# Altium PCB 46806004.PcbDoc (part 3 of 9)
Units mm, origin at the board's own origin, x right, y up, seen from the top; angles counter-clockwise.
Board outline 130 x 105 mm, 8 copper layers (Top Layer, P1-GND, L1-Signal, L2-Signal, L3-Signal, L4-Signal, P2-GND, Bottom Layer), stack 1.63 mm thick; 796 components, 496 nets, 2808 pads, 1195 vias.
Unrouted connection lines stored in the file: 1.
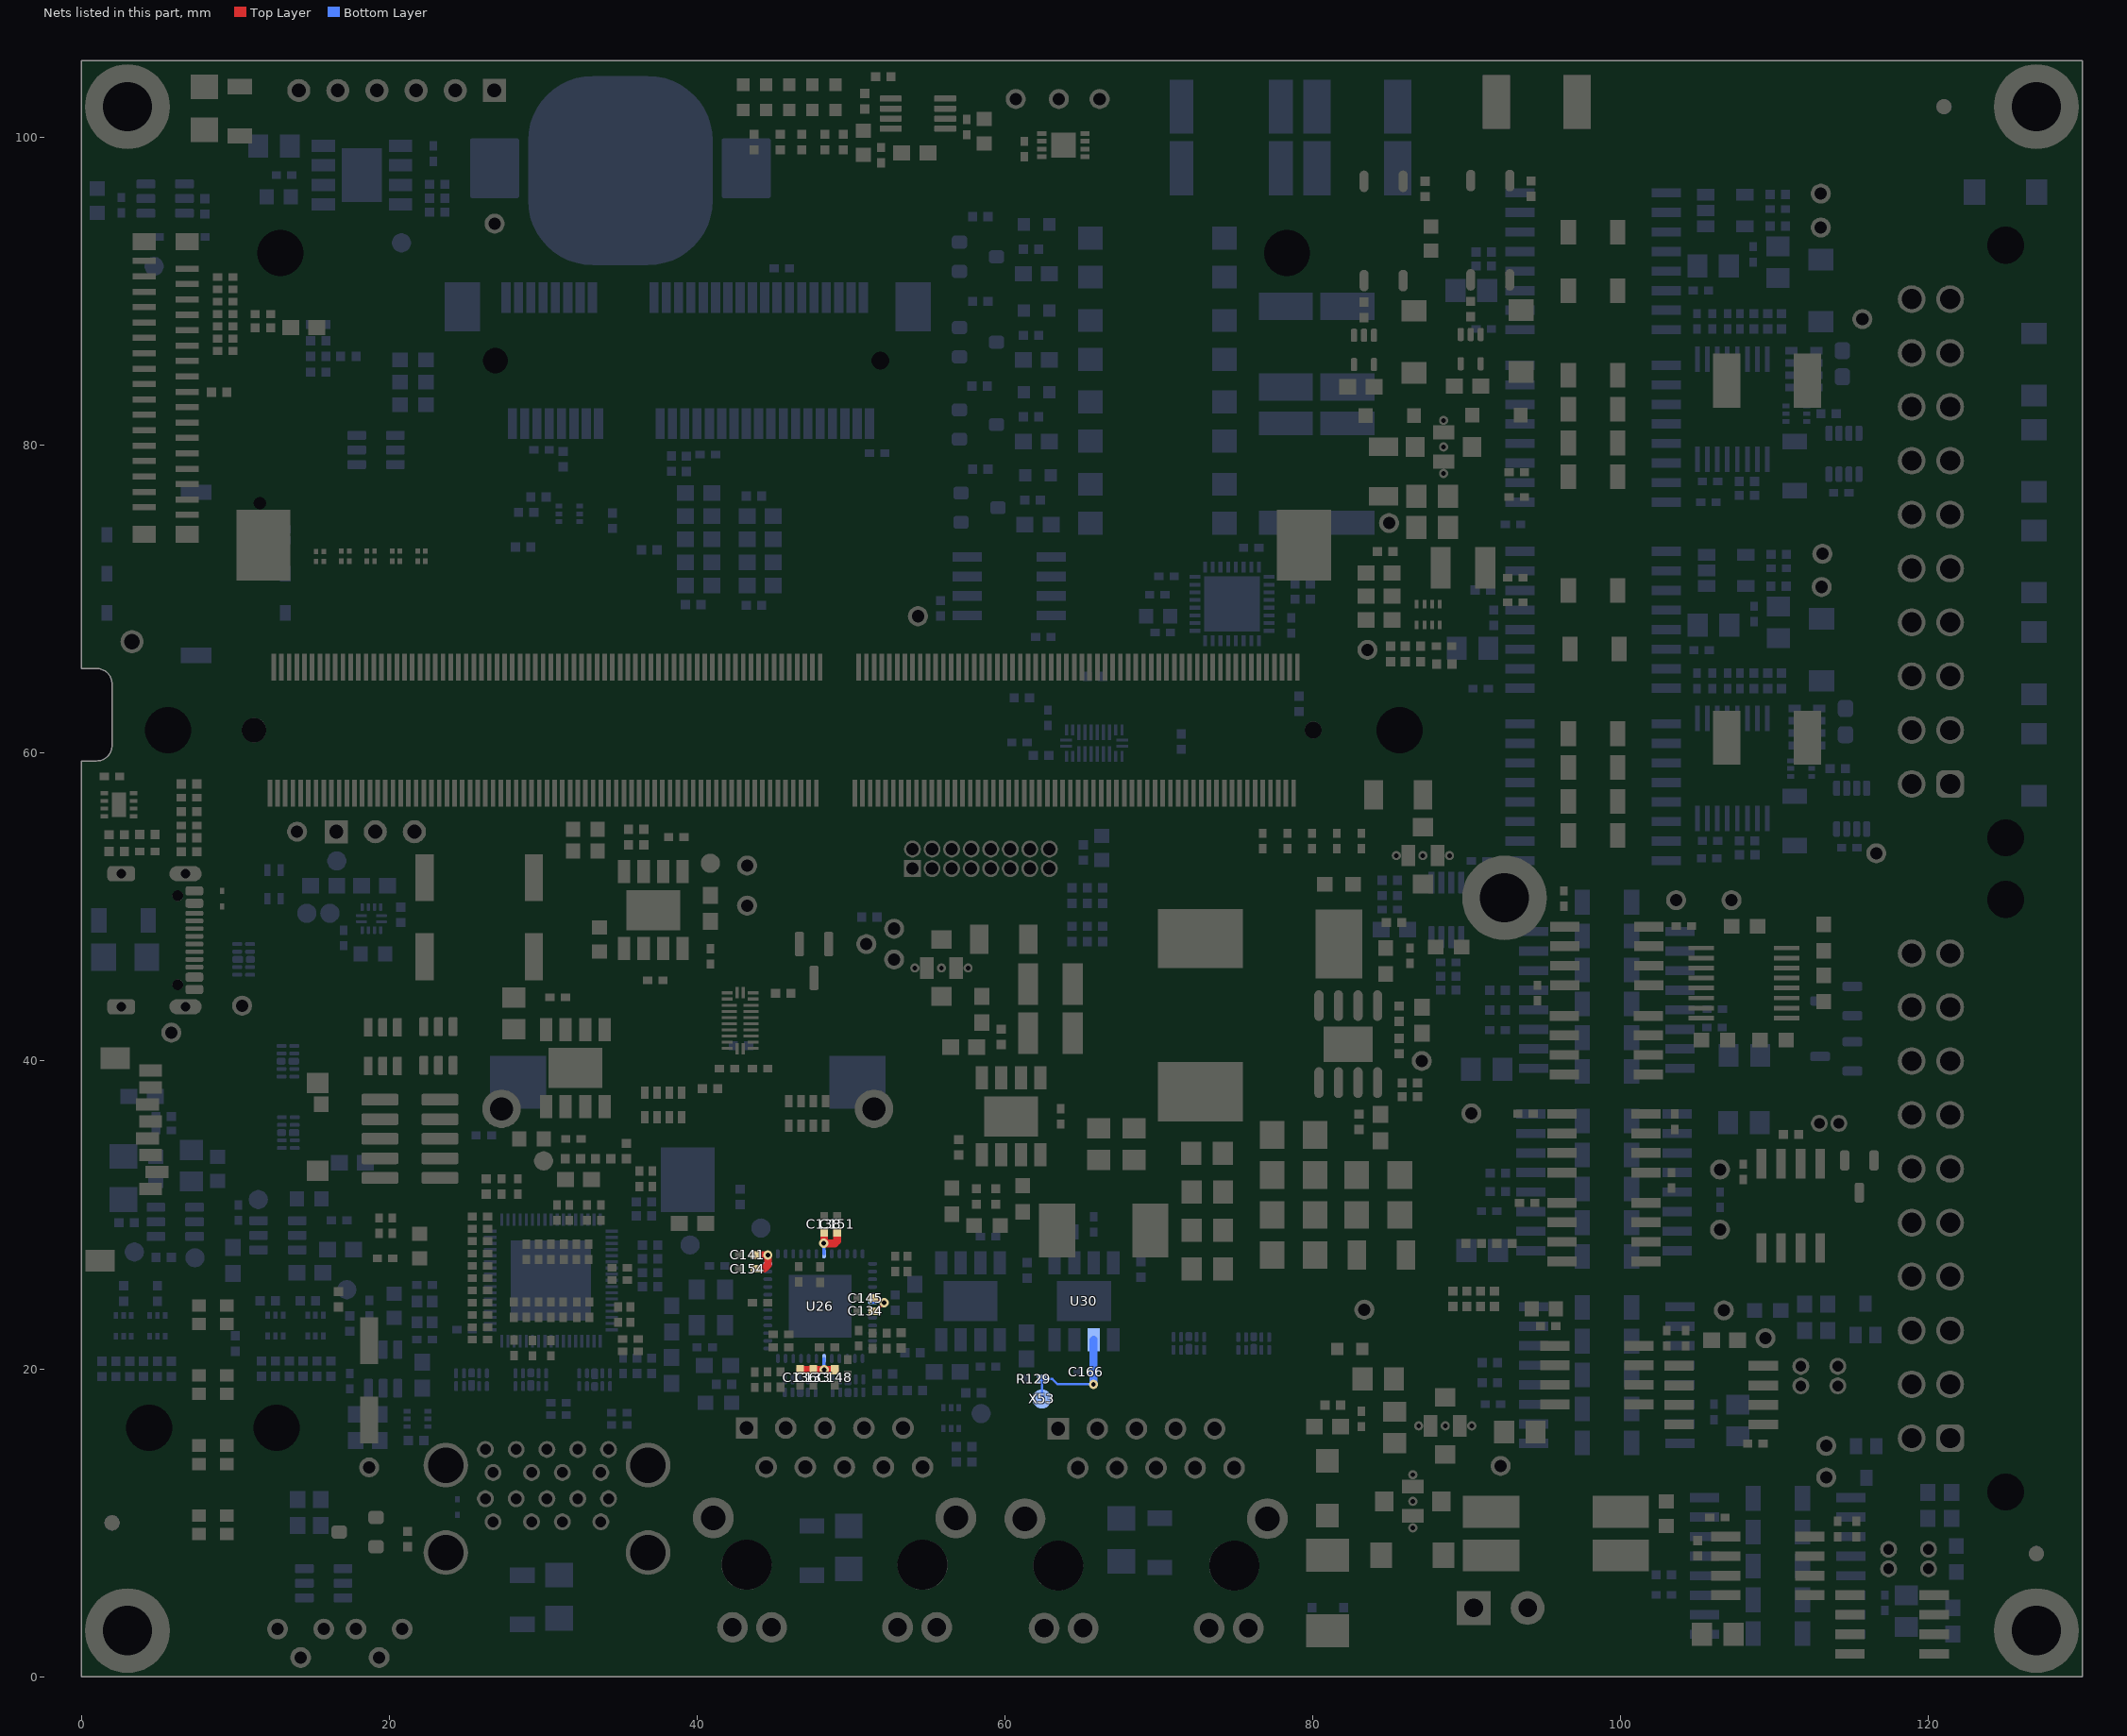
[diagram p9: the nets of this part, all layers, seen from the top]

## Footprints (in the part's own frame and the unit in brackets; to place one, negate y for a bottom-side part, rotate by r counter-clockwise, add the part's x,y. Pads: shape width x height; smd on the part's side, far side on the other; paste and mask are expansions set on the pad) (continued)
PW016 [mm] "16-TSSOP (0.173\", 4.40mm Width)"
  rect 0.3x1.65 smd: 1(-2.275,-2.775) 2(-1.625,-2.775) 3(-0.975,-2.775) 4(-0.325,-2.775) 5(0.325,-2.775) 6(0.975,-2.775) 7(1.625,-2.775) 8(2.275,-2.775) 9(2.275,2.775) 10(1.625,2.775) 11(0.975,2.775) 12(0.325,2.775) 13(-0.325,2.775) 14(-0.975,2.775) 15(-1.625,2.775) 16(-2.275,2.775)
  silkscreen extent -2.97,-2.89 2.55,1.55, body extent -2.55,-3.3 2.55,3.3, height 1.2
QFN40P160X160X40-12N [mm] "12-X2QFN (1.6x1.6), 12-Leads, Body 1,60x1,60mm, Pitch 0,40mm, IPC Medium Density"
  rrect50% 0.7x0.2 smd: 1(-0.65,0.2) 2(-0.65,-0.2) 7(0.65,-0.2) 8(0.65,0.2)
  rrect50% 0.2x0.5 smd: 3(-0.6,-0.75) 4(-0.2,-0.75) 5(0.2,-0.75) 6(0.6,-0.75) 9(0.6,0.75) 10(0.2,0.75) 11(-0.2,0.75) 12(-0.6,0.75)
  silkscreen extent -1.4,-1.19 1.19,1.19, body extent -0.8,-0.8 0.8,0.8, height 0.4
QFN50P500X500X90-33N-V [mm] "QFN,0.50mm pitch,square;32 pin,5.00mm L X 5.00mm W X 0.90mm H body (w/thermal tab)"
  rect 0.7x0.25 smd paste+0 mask+0: 1(-2.4,1.75) 2(-2.4,1.25) 3(-2.4,0.75) 4(-2.4,0.25) 5(-2.4,-0.25) 6(-2.4,-0.75) 7(-2.4,-1.25) 8(-2.4,-1.75) 17(2.4,-1.75) 18(2.4,-1.25) 19(2.4,-0.75) 20(2.4,-0.25) 21(2.4,0.25) 22(2.4,0.75) 23(2.4,1.25) 24(2.4,1.75)
  rect 0.25x0.7 smd paste+0 mask+0: 9(-1.75,-2.4) 10(-1.25,-2.4) 11(-0.75,-2.4) 12(-0.25,-2.4) 13(0.25,-2.4) 14(0.75,-2.4) 15(1.25,-2.4) 16(1.75,-2.4) 25(1.75,2.4) 26(1.25,2.4) 27(0.75,2.4) 28(0.25,2.4) 29(-0.25,2.4) 30(-0.75,2.4) 31(-1.25,2.4) 32(-1.75,2.4)
  rect 3.6x3.6 smd paste-20 mask+0: 33(0,0)
  silkscreen extent -3.42,-2.5 2.5,2.5, body extent -2.5,-2.5 2.5,2.5, height 0.9
QFN68_LT68B_CYP [mm]
  rect 0.808x0.204 smd paste+0 mask+0: 1(-3.947,3.2) 2(-3.947,2.8) 3(-3.947,2.4) 4(-3.947,2) 5(-3.947,1.6) 6(-3.947,1.2) 7(-3.947,0.8) 8(-3.947,0.4) 9(-3.947,0) 10(-3.947,-0.4) 11(-3.947,-0.8) 12(-3.947,-1.2) 13(-3.947,-1.6) 14(-3.947,-2) 15(-3.947,-2.4) 16(-3.947,-2.8) 17(-3.947,-3.2) 35(3.947,-3.2) 36(3.947,-2.8) 37(3.947,-2.4) 38(3.947,-2) 39(3.947,-1.6) 40(3.947,-1.2) 41(3.947,-0.8) 42(3.947,-0.4) 43(3.947,0) 44(3.947,0.4) 45(3.947,0.8) 46(3.947,1.2) 47(3.947,1.6) 48(3.947,2) 49(3.947,2.4) 50(3.947,2.8) 51(3.947,3.2)
  rect 0.204x0.808 smd paste+0 mask+0: 18(-3.2,-3.947) 19(-2.8,-3.947) 20(-2.4,-3.947) 21(-2,-3.947) 22(-1.6,-3.947) 23(-1.2,-3.947) 24(-0.8,-3.947) 25(-0.4,-3.947) 26(0,-3.947) 27(0.4,-3.947) 28(0.8,-3.947) 29(1.2,-3.947) 30(1.6,-3.947) 31(2,-3.947) 32(2.4,-3.947) 33(2.8,-3.947) 34(3.2,-3.947) 52(3.2,3.947) 53(2.8,3.947) 54(2.4,3.947) 55(2,3.947) 56(1.6,3.947) 57(1.2,3.947) 58(0.8,3.947) 59(0.4,3.947) 60(0,3.947) 61(-0.4,3.947) 62(-0.8,3.947) 63(-1.2,3.947) 64(-1.6,3.947) 65(-2,3.947) 66(-2.4,3.947) 67(-2.8,3.947) 68(-3.2,3.947)
  rect 5.207x5.207 smd paste-2.591 mask+0: 69(0,0)
  silkscreen extent -4.86,-4.86 4.86,4.86, body extent -4.05,-4.05 4.05,4.05, height 0.99
R0402_RESC1005L [mm] "Chip Resistor, Body 1.1x0.5mm, IPC High Density"
  rect 0.6x0.6 smd: 1(-0.5,0) 2(0.5,0)
  body extent -0.5,-0.25 0.5,0.25, height 0.35
R/0603 [mm] "RES 1/10W 0603"
  rect 1.1x1 smd: 1(-0.85,0) 2(0.85,0)
  silkscreen extent -1.65,-0.75 1.65,0.75, body extent -0.8,-0.4 0.8,0.4, height 0.45
R/0805 [mm] "RES 1/4W 0805 / From http://www.vishay.com/docs/28745/soldpads.pdf"
  rect 1.3x1.5 smd: 1(-1.025,0) 2(1.025,0)
  silkscreen extent -1.91,-0.99 1.91,0.99, body extent -1.15,-0.67 1.15,0.67, height 0.76
R/1206 [mm] "1206 (3216 Metric)"
  rect 1x1.6 smd: 1(-1.6,0) 2(1.6,0)
  silkscreen extent -2.36,-1.09 2.36,1.09, body extent -1.51,-0.77 1.51,0.77, height 0.55
R/2512 [mm] "2512 (6432 Metric)"
  rect 1.55x3.5 smd: 1(-3.225,0) 2(3.225,0)
  silkscreen extent -4.24,-2 4.24,2, body extent -3.2,-1.6 3.2,1.6, height 0.6
RESNET-1206-4 [mm]
  rect 0.5x0.8 smd: 1(-1.2,-0.8) 2(-0.4,-0.8) 3(0.4,-0.8) 4(1.2,-0.8) 5(1.2,0.8) 6(0.4,0.8) 7(-0.4,0.8) 8(-1.2,0.8)
  silkscreen extent -1.75,-0.87 1.7,0.87, body extent -1.6,-0.8 1.6,0.8, height 0.57
RGZ0048B [mm] "48-VQFN (7x7) (RGZ) Exposed Pad with vias"
  oval 0.6x0.24 smd paste+0 mask+0.051: 1(-3.4,2.75) 2(-3.4,2.25) 3(-3.4,1.75) 4(-3.4,1.25) 5(-3.4,0.75) 6(-3.4,0.25) 7(-3.4,-0.25) 8(-3.4,-0.75) 9(-3.4,-1.25) 10(-3.4,-1.75) 11(-3.4,-2.25) 12(-3.4,-2.75) 25(3.4,-2.75) 26(3.4,-2.25) 27(3.4,-1.75) 28(3.4,-1.25) 29(3.4,-0.75) 30(3.4,-0.25) 31(3.4,0.25) 32(3.4,0.75) 33(3.4,1.25) 34(3.4,1.75) 35(3.4,2.25) 36(3.4,2.75)
  oval 0.24x0.6 smd paste+0 mask+0.051: 13(-2.75,-3.4) 14(-2.25,-3.4) 15(-1.75,-3.4) 16(-1.25,-3.4) 17(-0.75,-3.4) 18(-0.25,-3.4) 19(0.25,-3.4) 20(0.75,-3.4) 21(1.25,-3.4) 22(1.75,-3.4) 23(2.25,-3.4) 24(2.75,-3.4) 37(2.75,3.4) 38(2.25,3.4) 39(1.75,3.4) 40(1.25,3.4) 41(0.75,3.4) 42(0.25,3.4) 43(-0.25,3.4) 44(-0.75,3.4) 45(-1.25,3.4) 46(-1.75,3.4) 47(-2.25,3.4) 48(-2.75,3.4)
  rect 4.1x4.1 smd paste-2.037 mask+0.051: 49(0,0)
  silkscreen extent -3.72,-3.72 3.72,3.72, body extent -3.5,-3.5 3.5,3.5, height 1
SAMTEC_FTSH-105-01-L-DV-K-TR [mm]
  rrect30% 0.76x2.4 smd: 1(-2.54,-1.95) 2(-2.54,1.95) 3(-1.27,-1.95) 4(-1.27,1.95) 5(0,-1.95) 6(0,1.95) 7(1.27,-1.95) 8(1.27,1.95) 9(2.54,-1.95) 10(2.54,1.95)
  silkscreen extent -3.43,-4.04 3.43,3.43, body extent -3.17,-2.92 3.18,2.92, height 6.1
Short_040 [mm]
  rrect50% 1.1x1 smd paste-2539.97 mask-2539.97: 1(-0.85,0) 2(0.85,0)
  Top Layer pour cut-out: -0.635,-0.508 0.635,-0.508 0.635,0.508 -0.635,0.508
  Top Layer region: -1.143,-0.381 1.143,-0.381 1.143,0.381 -1.143,0.381
SIM8055611400A [mm] "SIM NANO PUSH PULL 6P, 1.35MM"
  rect 1x0.7 smd: C1(2.54,-5.795) C2(0,-5.795) C3(-2.54,-5.795) C6(0,5.795) C7(-2.54,5.795)
  rect 0.5x0.7 smd: C5(2.19,5.795) CD(2.89,5.795)
  round 0.7 hole 0.8 unplated: MH1(4.6,4.15)
  round 1.5 hole 1: MH2(-4.4,-4.15)
  rect 1x2 smd: MP1(5.3,0) MP2(-5.3,0)
  Top Layer keep-out region: 3.15,2.953 1.95,2.953 1.95,3.953 3.15,3.953
  Top Layer keep-out region: 0.603,2.95 -0.597,2.95 -0.597,3.95 0.603,3.95
  Top Layer keep-out region: -1.937,2.95 -3.137,2.95 -3.137,3.95 -1.937,3.95
  Top Layer keep-out region: 1.943,-2.95 3.143,-2.95 3.143,-3.95 1.943,-3.95
  Top Layer keep-out region: -0.597,-2.95 0.603,-2.95 0.603,-3.95 -0.597,-3.95
  Top Layer keep-out region: -3.137,-2.95 -1.937,-2.95 -1.937,-3.95 -3.137,-3.95
  Top Layer keep-out region: -3.572,2.425 3.578,2.425 3.578,-2.425 -3.572,-2.425
  silkscreen extent -4.77,-6.7 4.77,6.1, body extent -5.4,-6.1 5.4,6.1, height 1.35
SMAJ [mil] "Diode SMA J-lead / DO-214AC SMA"
  rect 60x58 smd: 1(-70,0) 2(70,0)
  silkscreen extent -111,-63 125,63, body extent -102,-51 102,51, height 95
SMAJ_TRANSIL [mm] "Diode SMA J-lead Transil / DO-214AC SMA"
  rect 1.4x1.64 smd: 1(-2.015,0) 2(2.015,0)
  silkscreen extent -2.92,-1.6 3.28,1.6, body extent -2.6,-1.3 2.6,1.3, height 2.4
SOD123_ALT [mm] "SOD-123; 2 Leads; Body 2.7 x 1.6 mm, (LxW)"
  rect 0.9x0.95 smd: 1(-1.575,0) 3(1.575,0)
  silkscreen extent -1.45,-0.85 1.45,0.85, body extent -1.85,-0.8 1.85,0.8, height 1.27
SOD923_DIO [mm] "Diode, SOD-923, CASE 514AA"
  rect 0.393x0.3 smd paste+0 mask+0: 1(-0.507,0) 2(0.507,0)
  Top Layer keep-out region: -0.15,-0.249 -0.15,0.249 0.15,0.249 0.15,-0.249
  body extent -0.53,-0.32 0.53,0.32, height 0.43
SOIC-8 [mil] "8-SOIC (0.154\", 3.90mm Width)"
  rect 75x25 smd: 1(-107.5,75) 2(-107.5,25) 3(-107.5,-25) 4(-107.5,-75) 5(107.5,-75) 6(107.5,-25) 7(107.5,25) 8(107.5,75)
  silkscreen extent -67,-100 35,110, body extent -118,-96 118,96, height 67
SOIC-16 [mm] "SOIC127P1030X265-16M_[SOIC-16W]_JEDEC_MS-013AA"
  rect 0.6x1.9 smd: 1(-4.445,-4.75) 2(-3.175,-4.75) 3(-1.905,-4.75) 4(-0.635,-4.75) 5(0.635,-4.75) 6(1.905,-4.75) 7(3.175,-4.75) 8(4.445,-4.75) 9(4.445,4.75) 10(3.175,4.75) 11(1.905,4.75) 12(0.635,4.75) 13(-0.635,4.75) 14(-1.905,4.75) 15(-3.175,4.75) 16(-4.445,4.75)
  silkscreen extent -5.42,-4.87 5.23,3.4, body extent -5.25,-5.32 5.25,5.32, height 2.66
SOP254P700X210-4N [mm] "SOP, 4-Leads, Body 3,70x4,55mm, Pitch 2,54mm, IPC Medium Density"
  oval 1.4x0.6 smd: 1(-3.225,1.27) 2(-3.225,-1.27) 3(3.225,-1.27) 4(3.225,1.27)
  silkscreen extent -3.3,-1.85 2.27,1.85, body extent -3.5,-1.85 3.5,1.85, height 2.3
"SOP-9 TP" [mm] "SOIC, 8-Leads, Body 5,0x4,0mm (max), Pitch 1,27mm, IPC Medium Density"
  oval 2x0.6 smd: 1(-2.5,1.905) 2(-2.5,0.635) 3(-2.5,-0.635) 4(-2.5,-1.905) 5(2.5,-1.905) 6(2.5,-0.635) 7(2.5,0.635) 8(2.5,1.905)
  rect 2.3x3.2 smd: 9(0,0)
  silkscreen extent -2.52,-2.5 0.9,2.88, body extent -3,-2.45 3,2.45, height 2.05
"SOP-9 TP_ALT" [mm] "SOIC, 8-Leads, Body 5,0x4,0mm (max), Pitch 1,27mm, IPC Medium Density"
  rect 1.505x0.802 smd: 1(-2.5,1.905) 2(-2.5,0.635) 3(-2.5,-0.635) 4(-2.5,-1.905) 5(2.5,-1.905) 6(2.5,-0.635) 7(2.5,0.635) 8(2.5,1.905)
  rect 2.613x3.502 smd: 9(0,0)
  silkscreen extent -2.52,-2.5 0.9,2.88, body extent -3,-2.45 3,2.45, height 1.45
SOT23 [mm]
  rrect50% 0.85x1 smd: 1(-0.95,-1.2) 2(0.95,-1.2) 3(0,1.2)
  silkscreen extent -1.9,-1.32 1.28,1.2, body extent -1.45,-1.4 1.45,1.4, height 1.3
SOT23-5 [mil] "SOT23-5, JEDEC MO-178 variation AA, 5-lead SMD package, most material condition"
  rect 30x45 smd: 1(-40,-50) 2(0,-50) 3(40,-50) 4(40,50) 5(-40,50)
  silkscreen extent -89,-87 65,87, body extent -57,-55 57,55, height 57
SOT23-6 [mm]
  rrect25% 0.58x1.21 smd: 1(-0.95,-1.255) 2(0,-1.255) 3(0.95,-1.255) 4(0.95,1.255) 5(0,1.255) 6(-0.95,1.255)
  silkscreen extent -1.73,-1.37 1.56,0.8, body extent -1.45,-1.4 1.45,1.4, height 1.45
sot23-6 [mm]
  rrect25% 0.58x1.21 smd: 1(-0.95,-1.255) 2(0,-1.255) 3(0.95,-1.255) 4(0.95,1.255) 5(0,1.255) 6(-0.95,1.255)
  silkscreen extent -1.73,-1.37 1.56,0.8, body extent -1.45,-1.4 1.45,1.4, height 1.45
SOT23_M [mm]
  rrect50% 1.6x0.6 smd: 1(-1.1,0.95) 2(-1.1,-0.95) 3(1.1,0)
  silkscreen extent -1.22,-1.5 0.7,1.93, body extent -1.4,-1.45 1.4,1.45, height 1.3
SOT23_N [mm] "SOT23, 3-Leads, Body 2.9x1.3mm, Pitch 0.95mm, Lead Span 2.3mm, IPC Medium Density"
  rrect50% 1.3x0.6 smd: 1(-1.05,0.95) 2(-1.05,-0.95) 3(1.05,0)
  silkscreen extent -1.18,-1.5 0.7,1.92, body extent -1.4,-1.45 1.4,1.45, height 1.3
SOT353-5N [mm] "SOT353, SC70, 5-Leads, Body 2x1.3mm, Pitch 0.65mm, Lead Span 2.1mm, IPC Medium Density"
  rrect50% 0.85x0.4 smd: 1(-0.95,0.65) 2(-0.95,0) 3(-0.95,-0.65) 4(0.95,-0.65) 5(0.95,0.65)
  silkscreen extent -1.07,-1.1 0.18,1.32, body extent -1.2,-1.1 1.2,1.1, height 1.1
SOT563 [mm]
  rect 0.45x0.3 smd: 1(-0.675,0.5) 2(-0.675,0) 3(-0.675,-0.5) 4(0.675,-0.5) 5(0.675,0) 6(0.675,0.5)
  silkscreen extent -1.18,-0.66 0.24,0.66, body extent -0.81,-0.8 0.81,0.8, height 0.59
SOT-323 [mm] "SOT-323/SC-70; 3 Leads; Body 2.2 x 2.2 mm, inc. leads (LxW max)"
  rect 0.8x1.05 smd: 1(-0.65,-1.025) 2(0.65,-1.025) 3(0,1.025)
  silkscreen extent -1.52,-1.17 1.1,0.89, body extent -1.1,-1.12 1.1,1.12, height 1.1
"T_AMPHENOL_ GSB311231HR" [mm]
  round 1.1 hole 0.7: L1(-3.5,-1.35) L2(-1,-1.35) L3(1,-1.35) L4(3.5,-1.35) L5(4,0.15) L6(2,0.15) L7(0,0.15) L8(-2,0.15) L9(-4,0.15) U1(-3.5,1.85) U2(-1,1.85) U3(1,1.85) U4(3.5,1.85) U5(4,3.35) U6(2,3.35) U7(0,3.35) U8(-2,3.35) U9(-4,3.35)
  round 2.9 hole 2.3: S1(-6.57,-3.35) S2(-6.57,2.33) S3(6.57,2.33) S4(6.57,-3.35)
  silkscreen extent -6.8,-11.02 6.8,4.72, body extent -7.79,-15.13 7.79,4.57, height 16.13
T_KEYSTONE_3000 [mm] "Battery Holder"
  rrect70% 12x12.3 smd paste-11: 1(0,-0.15)
  rrect10% 3.2x3.9 smd: 2(-8.17,0) 2(8.17,0)
  silkscreen extent -6.63,-6.75 6.63,6.3, body extent -9.47,-6.72 9.47,5.34, height 3.16
T_TORADEX_LOGO [mm] "Toradex Logo in copper, no soldermask"
  Top Layer lines w0.15: -7.115,-0.198 cw(c-7.136,-0.05) -7.286,-0.05 cw(c-7.136,-0.05) -7.115,0.099 ; -7.116,-0.05 -7,-0.05 ; -7.044,-0.26 ccw(c-6.322,-0.05) -5.621,-0.319 ; -7.044,0.16 cw(c-6.322,-0.05) -5.621,0.22 ; -6.911,-0.118 ccw(c-7.104,-0.277) -7,-0.05 ; -6.911,0.019 cw(c-7.104,0.178) -7,-0.05 ; -6.764,-0.4 ccw(c-6.322,-0.05) -5.955,-0.477 cw(c-5.738,-0.05) -6.087,-0.379 cw(c-6.436,-0.05) -6.916,-0.05 cw(c-6.436,-0.05) -6.087,0.28 cw(c-5.738,-0.05) -5.955,0.378 ccw(c-6.322,-0.05) -6.764,0.301 ; -6.484,-0.59 ccw(c-6.436,-0.05) -6.087,-0.465 ccw(c-5.738,-0.05) -6.067,-0.481 cw(c-6.322,-0.05) -6.192,-0.533 ; -6.484,0.491 cw(c-6.436,-0.05) -6.087,0.366 cw(c-5.738,-0.05) -6.067,0.382 ccw(c-6.322,-0.05) -6.192,0.434 ; -5.636,-0.331 cw(c-5.738,-0.05) -5.636,0.232 ; 4.083,-0.046 4.702,-0.046 5.383,-0.046 ccw(c4.702,-0.05) 5.214,-0.499 ; 4.087,-0.116 4.702,-0.116 5.45,-0.116 ccw(c4.702,-0.05) 5.304,-0.499 5.127,-0.499 cw(c4.702,-0.05) 5.317,0.017 4.702,0.017 4.087,0.017 ; -7.241,-0.05 ccw(c-7.136,-0.05) -7.121,-0.153 ; -7.241,-0.05 ccw(c-7.136,-0.05) -7.121,-0.153 ; -7.241,-0.05 cw(c-7.136,-0.05) -7.121,0.054 ccw(c-7.104,0.178) -6.984,0.143 cw(c-6.322,-0.05) -5.732,0.305 ccw(c-5.738,-0.05) -6.087,0.015 ccw(c-6.436,-0.05) -6.087,-0.114 ccw(c-5.738,-0.05) -5.732,-0.404 cw(c-6.322,-0.05) -6.984,-0.242 ccw(c-7.104,-0.277) -7.121,-0.153 ; -7.178,-0.05 ccw(c-7.136,-0.05) -7.13,-0.091 cw(c-7.104,-0.277) -6.924,-0.225 ccw(c-6.322,-0.05) -5.844,-0.453 cw(c-5.738,-0.05) -6.087,-0.278 cw(c-6.436,-0.05) -6.087,0.179 cw(c-5.738,-0.05) -5.844,0.354 ccw(c-6.322,-0.05) -6.924,0.126 cw(c-7.104,0.178) -7.13,-0.008 ccw(c-7.136,-0.05) -7.178,-0.05 ; -6.736,-0.05 cw(c-6.436,-0.05) -6.136,-0.05 cw(c-6.436,-0.05) -6.736,-0.05 ; -5.194,-0.05 ccw(c-5.044,-0.05) -4.894,-0.05 ccw(c-5.044,-0.05) -5.194,-0.05 ; -5.149,-0.05 cw(c-5.044,-0.05) -4.939,-0.05 cw(c-5.044,-0.05) -5.149,-0.05 ; -5.086,-0.05 ccw(c-5.044,-0.05) -5.002,-0.05 ccw(c-5.044,-0.05) -5.086,-0.05 ; -4.498,-0.05 ccw(c-4.348,-0.05) -4.198,-0.05 ccw(c-4.348,-0.05) -4.498,-0.05 ; -4.453,-0.05 cw(c-4.348,-0.05) -4.243,-0.05 cw(c-4.348,-0.05) -4.453,-0.05 ; -4.39,-0.05 ccw(c-4.348,-0.05) -4.306,-0.05 ccw(c-4.348,-0.05) -4.39,-0.05 ; -4.322,0.994 -3.523,0.994 -3.523,-0.75 -3.372,-0.75 -3.372,0.994 -2.603,0.994 -2.603,1.125 -4.218,1.125 -4.322,0.994 ; -4.192,1.057 -3.46,1.057 -3.46,-0.688 -3.434,-0.688 -3.434,1.057 -2.665,1.057 -2.665,1.062 -4.188,1.062 -4.192,1.057 ; -2.827,-0.05 ccw(c-2.076,-0.05) -1.324,-0.05 ccw(c-2.076,-0.05) -2.827,-0.05 ; -2.764,-0.05 ccw(c-2.076,-0.05) -1.387,-0.05 ccw(c-2.076,-0.05) -2.764,-0.05 ; -2.694,-0.05 ccw(c-2.076,-0.05) -1.457,-0.05 ccw(c-2.076,-0.05) -2.694,-0.05 ; -0.939,-0.75 -0.806,-0.75 -0.806,-0.05 cw(c-0.188,-0.05) -0.009,0.542 cw(c0.958,-0.05) 0.071,0.656 ccw(c-0.188,-0.05) -0.939,-0.05 -0.939,-0.75 ; -0.877,-0.688 -0.869,-0.688 -0.869,-0.05 cw(c-0.188,-0.05) -0.037,0.615 cw(c0.958,-0.049) -0.032,0.621 ccw(c-0.188,-0.05) -0.877,-0.05 -0.877,-0.688 ; 0.207,-0.05 ccw(c0.958,-0.05) 1.576,-0.476 1.576,-0.75 1.709,-0.75 1.709,-0.05 ccw(c0.958,-0.05) 0.207,-0.05 ; 0.269,-0.05 ccw(c0.958,-0.05) 1.639,-0.153 1.639,-0.688 1.647,-0.688 1.647,-0.05 ccw(c0.958,-0.05) 0.269,-0.05 ; 0.339,-0.05 ccw(c0.958,-0.05) 1.576,-0.05 ccw(c0.958,-0.05) 0.339,-0.05 ; 2.053,-0.05 cw(c2.804,-0.05) 3.423,0.377 3.423,1.125 3.556,1.125 3.556,-0.05 cw(c2.804,-0.05) 2.053,-0.05 ; 2.116,-0.05 cw(c2.804,-0.05) 3.485,0.054 3.485,1.062 3.493,1.062 3.493,-0.05 cw(c2.804,-0.05) 2.116,-0.05 ; 2.186,-0.05 ccw(c2.804,-0.05) 3.423,-0.05 ccw(c2.804,-0.05) 2.186,-0.05 ; 5.623,-0.75 5.791,-0.75 6.314,-0.086 6.835,-0.75 6.995,-0.75 6.403,0.006 6.919,0.664 6.749,0.664 6.314,0.1 5.879,0.664 5.716,0.664 6.23,0.006 5.623,-0.75 ; 5.753,-0.688 5.761,-0.688 6.315,0.015 6.865,-0.688 6.866,-0.688 6.323,0.006 6.79,0.602 6.78,0.602 6.314,-0.002 5.849,0.602 5.844,0.602 6.309,0.005 5.753,-0.688
TestPoint_1 [mm]
  round 1.3 hole 0.8: 1(0,0)
  silkscreen extent -0.9,-0.9 0.9,0.9
TestPoint_3 [mm]
  round 1.25 smd paste-1.25: 1(0,0)
TLP241A_TP1 [mm] "TOSHIBA TLP241A_TP1"
  rect 1.6x1.5 smd paste+0 mask+0: 1(-4.35,1.27) 2(-4.35,-1.27) 3(4.35,-1.27) 4(4.35,1.27)
  silkscreen extent -4.85,-2.54 3.45,2.55, body extent -5,-2.41 5,2.41, height 4.24
TSOT-23-8_TEX [mil] "SOT-23-8, TSOT-23-8, Texas DDF0008A"
  rrect50% 39.5x18 smd paste-1.97 mask+3.94: 1(-52.25,38.39) 2(-52.25,12.8) 3(-52.25,-12.79) 4(-52.25,-38.38) 5(52.25,-38.38) 6(52.25,-12.79) 7(52.25,12.8) 8(52.25,38.39)
  silkscreen extent -58,-63 38,67, body extent -55,-57 55,57, height 39
TSSO3x5-G8/X.35 [mm] "TSSOP-8P065 Shrink Small Outline; 8 Leads; Body Width 3 mm; Pitch 0.65 mm"
  rrect25% 0.4x1.42 smd: 1(-0.975,-1.77) 2(-0.325,-1.77) 3(0.325,-1.77) 4(0.975,-1.77) 5(0.975,1.77) 6(0.325,1.77) 7(-0.325,1.77) 8(-0.975,1.77)
  silkscreen extent -1.65,-2.11 1.52,0.8, body extent -1.47,-2 1.47,2, height 1.3
TSSOP16 [mm]
  rect 1.65x0.3 smd: 1(-3.25,2.275) 2(-3.25,1.625) 3(-3.25,0.975) 4(-3.25,0.325) 5(-3.25,-0.325) 6(-3.25,-0.975) 7(-3.25,-1.625) 8(-3.25,-2.275) 9(3.25,-2.275) 10(3.25,-1.625) 11(3.25,-0.975) 12(3.25,-0.325) 13(3.25,0.325) 14(3.25,0.975) 15(3.25,1.625) 16(3.25,2.275)
  silkscreen extent -2.89,-2.55 1.55,2.97, body extent -3.3,-2.55 3.3,2.55, height 1.2
UQFN-24 [mm]
  rect 0.7x0.2 smd paste-0.337 mask+0.05: 1(-0.85,1.8) 2(-0.85,1.4) 9(-0.85,-1.4) 10(-0.85,-1.8) 13(0.85,-1.8) 14(0.85,-1.4) 21(0.85,1.4) 22(0.85,1.8)
  rect 1x0.2 smd paste-0.487 mask+0.05: 3(-0.7,1) 4(-0.7,0.6) 5(-0.7,0.2) 6(-0.7,-0.2) 7(-0.7,-0.6) 8(-0.7,-1) 15(0.7,-1) 16(0.7,-0.6) 17(0.7,-0.2) 18(0.7,0.2) 19(0.7,0.6) 20(0.7,1)
  rect 0.2x0.75 smd paste-0.362 mask+0.05: 11(-0.2,-1.825) 12(0.2,-1.825) 23(0.2,1.825) 24(-0.2,1.825)
  silkscreen extent -1.88,-2.25 1.36,2.25, body extent -1,-2 1,2, height 0.55
WEIDMULLER_1728700000 [mm] "TERM BLOCK HDR 20POS 90DEG 3.5MM"
  rrect50% 1.8x1.8 hole 1.3 paste-2539.97: 1(-15.75,0.55)
  round 1.8 hole 1.3 paste-2539.97: 2(-15.75,3.05) 3(-12.25,0.55) 4(-12.25,3.05) 5(-8.75,0.55) 6(-8.75,3.05) 7(-5.25,0.55) 8(-5.25,3.05) 9(-1.75,0.55) 10(-1.75,3.05) 11(1.75,0.55) 12(1.75,3.05) 13(5.25,0.55) 14(5.25,3.05) 15(8.75,0.55) 16(8.75,3.05) 17(12.25,0.55) 18(12.25,3.05) 19(15.75,0.55) 20(15.75,3.05)
  round 0 hole 2.4 unplated paste-2539.97 mask-1.41: 21(-19.25,-3.05) 22(19.25,-3.05)
  silkscreen extent -21.68,-7.65 21.08,4.28, body extent -21,-10.05 21,4.15, height 10.5
WSON-8(2.1x2.1)_PAD [mm] "8-WFDFN Exposed Pad, 8-WSON (2x2), DSG0008A_TEX"
  rect 0.5x0.25 smd paste+0 mask+0: 1(-0.95,0.75) 2(-0.95,0.25) 3(-0.95,-0.25) 4(-0.95,-0.75) 5(0.95,-0.75) 6(0.95,-0.25) 7(0.95,0.25) 8(0.95,0.75)
  rect 0.9x1.6 smd paste-0.45 mask+0: 9(0,0)
  silkscreen extent -1.1,-1.15 1.07,1.4, body extent -1,-1 1,1, height 0.77
WURTH_9774025243R [mm] "SMT Steel Spacer with internal Thread M2, height 2.5mm"
  round 0 hole 3 unplated: 1(0,0)
  Top Layer circle w1: c0,0 r2.15
  Top Layer keep-out circle w0.05: c0,0 r2.85
  Bottom Layer keep-out circle w0.05: c0,0 r1.7
  body extent -2.17,-2.17 2.18,2.17, height 2.5
XTAL_CX3225 [mm] "KYOCERA"
  rect 1.3x1.05 smd mask+0.08: 1(-1.15,-0.925) 2(1.15,-0.925) 3(1.15,0.925) 4(-1.15,0.925)
  silkscreen extent -1.98,-1.63 0.2,1.47, body extent -1.6,-1.25 1.6,1.25, height 1.05

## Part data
C2 C102 C109 C163 C257: "CAP CER 1000PF 2KV X7R 1206", Mfr="Johanson Dielectrics Inc.", MfrNo=202R18W102KV4E, Supplier Part Number 1=709-1036-1-ND
C3 C67 C68 C69 C80: "(-55 to 125 DegC) CAP FEEDTHRU 1UF 20% 100V 1206 6A", Mfr="TDK Corporation", MfrNo=YFF31HC2A105MT000N, Supplier Part Number 1=445-16151-1-ND
C4 C5 C6 C7 C8 C12 C17 C21 C39 C58 C66 C86 C88 C89 C91 C123 C124 C158 C159 C165 C166 C174 C176 C180 C181 C239 C241 C242 C243 C253: library part 2404-Cap-0402-22uF/6.3V, "(-55 to 85 DegC) CAP CER 22UF 6.3V 20% X5R 0402", Mfr=Murata, MfrNo=GRM155R60J226ME11D, Supplier Part Number 1=C415703
C9 C10 C11 C13 C14 C15 C16 C25 C28 C30 C32 C36 C38 C44 C50 C62 C64 C82 C97 C100 C101 C103 C106 C108 C111 C114 C117 C118 C119 C120 C121 C122 C127 C128 C129 C130 C145 C147 C148 C150 C151 C152 C153 C154 C155 C157 C160 C167 C170 C171 C172 C173 C175 C182 C185 C186 C187 C188 C193 C194 C195 C196 C197 C198 C199 C201 C203 C204 C205 C206 C207 C208 C209 C210 C211 C213 C215 C216 C218 C219 C220 C221 C222 C223 C225 C227 C228 C229 C230 C231 C232 C244 C245 C246 C247 C248 C249 C250 C251 C252 C254 C256 C258 C259 C260: library part 1566-Cap-0402-100nF/50V, "(-55 to 125 DegC AEC) Cap Ceramic 0.1uF 50V X7R 10% 0402", Mfr=Murata, MfrNo=GRT155R71H104KE01D, Supplier Part Number 1=490-GRT155R71H104KE01DCT-ND
C18 C24 C29 C31 C33 C35 C37 C40 C42 C45 C46 C47 C51 C52 C53 C56 C57 C63 C65: library part 1149-Cap-0402-10nF/50V, "Cap Ceramic 10nF 50V X7R 10% 0402", Mfr=Yageo, MfrNo=CC0402KRX7R9BB103, Supplier Part Number 1=311-1349-2-ND
C19 C26 C43 C134 C136 C137 C138 C140 C141 C144 C146 C149 C161 C162: "Cap Ceramic 1uF 6.3V X5R 20% SMD 0402 85C T/R", Mfr=Samsung, MfrNo=CL05A105MQ5NNNC, Supplier Part Number 1=1276-1235-1-ND
C20 C27 C34 C41 C48 C49 C54 C55 C59 C60: "CAP CER 1000PF 50V 5% NP0 0402", Mfr="Samsung Electro-Mechanics America, Inc", MfrNo=CL05C102JB5NNNC, Supplier Part Number 1=1276-1635-1-ND
C22 C23: "CAP CER 12PF 50V 5% NP0 0402", Mfr="Samsung Electro-Mechanics America, Inc", MfrNo=CL05C120JB5NNNC, Supplier Part Number 1=1276-1178-1-ND
C61 C71 C74 C92 C94 C95 C96 C98 C99 C104 C115 C116 C125 C126 C191 C192 C200 C202 C212 C214 C217 C224 C226 C233 C240: "(-55 to 85 DegC) CAP CER 22uF 16V X5R 0805", Mfr=Samsung, MfrNo=CL21A226MOQNNNE, Supplier Part Number 1=1276-2909-1-ND
C70 C72 C75 C76 C78 C79: library part 1873-Cap-1206-2.2uF/100V, "(-55 to 125 DegC) CAP CER 2.2UF 100V 10% X7R 1206", Mfr=Yageo, Supplier Part Number 1=311-3450-1-ND
C73 C77: library part 1607-Cap-1206-10uF/50V, "(-55 to 85 DegC) CAP CER 10UF 50V 10% X5R 1210", Mfr=Samsung, MfrNo=CL31A106KBHNNNE, Supplier Part Number 1=1276-2876-1-ND
C81: "(-55 to 125 DegC) CAP CER 3600PF 50V C0G/NP0 0603", Mfr=Murata, MfrNo=GRM1885C1H362JA01D, Supplier Part Number 1=490-6386-1-ND
C83 C90 C183 C184 C189 C190: "(-55 to 125 Degc AEC) CAP CER 100PF 50V 5% NPO 0402", Mfr=Murata, MfrNo=GCM1555C1H101JA16D, Supplier Part Number 1=490-10669-1-ND
C84 C87: "Cap 0603 DNP"
C85 C93: "(-55 to 125 DegC) CAP CER 2.2nF 100V 10% X7R 0603", Mfr=KEMET, MfrNo=C0603C222K1RACTU, Supplier Part Number 1=399-C0603C222K1RAC7867CT-ND
C107: "(-55 to 85 DegC) CAP CER 100UF 6.3V X5R 1206", Mfr=Yageo, MfrNo=CC1206MKX5R5BB107, Supplier Part Number 1=311-1991-1-ND
C131 C132: "CAP CER 4700PF 50V 5% NP0 0603", Mfr="Murata Electronics North America", MfrNo=GRM1885C1H472JA01D, Supplier Part Number 1=490-9669-1-ND
C133 C135 C143 C164: "(-55 to 85 DegC) CAP CER 10UF 6.3V 20% X5R 0402", Mfr=Murata, MfrNo=GRM155R60J106ME44D, Supplier Part Number 1=490-13811-2-ND
C139 C142: "CAP CER 18PF 50V 5% NP0 0402", Mfr="Samsung Electro-Mechanics America, Inc", MfrNo=CL05C180JB5NNNC, Supplier Part Number 1=1276-1140-1-ND
C156 C177 C178 C179: "(-55 - 125 DegC) CAP CER 30PF 50V C0G/NP0 0603", Mfr="Kyocera AVX", MfrNo=06035A300JAT2A\4K, Supplier Part Number 1=478-7917-1-ND
C168 C169 C255: library part 2241-Cap-6.6x6.6-330uF/6.3V, "(-55 to 105 DegC) CAP ALUM POLY 33UF 6.3V 20% SMD 10mohm 6.6x6.6x6.1mm Ir:3.9A (100kHz)", Mfr="United Chemi-Con", MfrNo=APXF6R3ARA331MF61G, Supplier Part Number 1=565-APXF6R3ARA331MF61GCT-ND
C234 C235 C236 C237 C238: "CAP CER 1UF 25V 10% X5R 0603", Mfr=Yageo, MfrNo=CC0603KRX5R8BB105, Supplier Part Number 1=311-1445-1-ND
D1 D14 D15 D16 D17 D23 D24 D25 D26 D27 D28: library part 0581-SMAJ33CA, "(-55 to 150 DegC) TVS DIODE 33VWM Vbrm:36.7V Vcl:53.3V 400W SMA", Mfr="Vishay Semiconductor Diodes Division", MfrNo=SMAJ33CA-E3/5A, Supplier Part Number 1=SMAJ33CA-E3/5AGICT-ND
D2: library part 1164-SK510A, "(-55 to 150 DegC) DIODE SCHOTTKY 5A 100V DO-214AC SMA 850mV@5A", Mfr=MCC, MfrNo=SK510A-LTP, Supplier Part Number 1=SK510A-LTPMSCT-ND
D3: library part 2067-DT12A120P5-13, "(-55 to 150 DegC) DIODE SCHOTTKY 120V 12A PowerDI", Mfr=Diodes, MfrNo=SDT12A120P5-13, Supplier Part Number 1=31-SDT12A120P5-13CT-ND
D4 D6 D10 D11 D12 D13 D18 D20 D21 D22: library part "0333-LED Green 0603", "(-40 to 85 DegC) LED GREEN 0603 50mcd", Mfr=Kingbright, MfrNo=APT1608CGCK, Supplier Part Number 1=754-1116-1-ND
D5 D7 D8 D9: library part "2349-LED RGB 4SMD", "(-40 to 85 DegC) LED RGB 2.1mm x 1.9mm x 1mm 4SMD vf=2V Red, 2.6V Green, 2.7V Blue", Mfr=Broadcom, Supplier Part Number 1=516-ASMB-LTC3-0D335CT-ND
D19: library part 0859-BAV199, "(-65 to 150 DegC) DIODE ARRAY SeriesConnection 85V 140MA SOT23-3 Low Leakage Ilk=5nA", Mfr="Diodes Incorporated", MfrNo=BAV199-7-F, Supplier Part Number 1=BAV199-FDICT-ND
D29 D30: library part 1159-1N4148W, "(-55 to 150 DegC) DIODE GEN PURP 100V 300MA SOD123", Mfr=Diodes, MfrNo=1N4148W-7-F, Supplier Part Number 1=1N4148W-FDICT-ND
D31 D32: library part 1655-D5V0L1B2S9-7, "(-65 to 155 DegC) TVS DIODE Vwm:5V Vcl:14V@6A SOD-923", Mfr=Diodes, Supplier Part Number 1=D5V0L1B2S9-7DICT-ND
F1: library part "2235-Fuse 5A Slow 125V", "(-55 to 125 DegC AEC) FUSE BOARD MOUNT 5A SLOW 125VAC/VDC", Mfr=Bel, MfrNo=0680L5000-05, Supplier Part Number 1=530-0680L5000-05
FID1 FID2 FID3 FID4 FID5 FID6: library part 0000-Fiducial-round
H1 H2 H3 H4 H5: library part 000-Hole-125mil
J1: "Header, 6-Pin"
J2: library part "2240-CONN-HDR 8x2 16POS 1.27MM", "(-40 to 105 DegC) CONN HEADER VERT 8x2 16POS Shroud Latch Lock/Eject Hooks, Short 1.27MM SMT", Mfr="CNC Tech", Supplier Part Number 1=1175-2193-ND
J3: library part "1195-Conn-Molex 2-POS R/A", "(-40 to 105 DegC) TERM BLOCK HDR 2POS 90DEG RA 3.5MM 8A ScrewFlange Black", Mfr=Molex, Supplier Part Number 1=WM23188-ND
J4: library part 1660-Conn-USB-Type-C, "(-40 to 85 DegC) Conn USB TYPE C RA, 24 (16+8 Dummy) Position, SMT/TH", Mfr="Global Connector Technology", Supplier Part Number 1=2073-USB4105-GF-A-120CT-ND
J5 J6: library part 2319-Conn-Hdr-2x10pin-RA-Flanges, "(-50 to 100 DegC) TERM BLOCK HDR 20POS 90DEG 3.5MM", Mfr=Weidmuller, Supplier Part Number 1=281-1826-ND
J7 J10: library part 1380-Conn-RJ45-GBe, "(-40 to 85 DegC) CONN MAGJACK 1PORT 1000 BASE-T Isolated Taps", Mfr=Pulse, Supplier Part Number 1=1840-1005-ND
J8: library part 1390-Conn-MiniPCIe, "(-55 to 85 DegC) CONN MINI EXPRESS CARD 52POS SMD", Mfr="TE Connectivity", Supplier Part Number 1=A142273CT-ND
J9: library part 1401-Conn-NanoSIM, "(-40 to 85 DegC) CONN SIM NANO PUSH PULL 6P, 1.35mm height", Mfr="Global Connector Technology", Supplier Part Number 1=2073-SIM8055-6-1-14-00-ACT-ND
J11: library part 1391-Conn-MiniPCIe-Latch, "(-55 to 85 DegC) CONN MINI EXPRESS CARD LATCH SMD", Mfr="TE Connectivity", Supplier Part Number 1=A125031CT-ND
J12: library part 1776-Conn-MicroSD, "(-40 to 85 DegC) CONN MICRO SD CARD PUSH-PUSH R/A, OPEN", Mfr="Global Connector Technology", Supplier Part Number 1=2073-MEM2052-00-195-00-ACT-ND
J13: library part "2512-Conn-Header 5X2 SMT Vert", "(-55 to 125 DegC) CONN HEADER VERT 10POS 2x5 1.27MM SMT Gold Shroud", Mfr=Samtec, Supplier Part Number 1=SAM13166CT-ND
J14 J18 J19 J20 J21: library part "2350-CONN HEADER VERT 2POS 1.27MM", "(-40 to 105 DegC) CONN HEADER VERT 2POS 1.27MM GOLD", Mfr=Sullins, Supplier Part Number 1=S9014E-02-ND
J15: library part 2373-F314-1A7H1-11034, "(-40 to 105 DegC) CONN FFC SIDE 34POS 0.5MM VERT", Mfr="Amphenol ICC / FCI", Supplier Part Number 1=609-F314-1A7H1-11034CT-ND
J16: library part 1820-Conn-USB3-2x-RA, "(-40 to 85 DegC) Conn USB 3.1 Type A R/A TH", Mfr="Amphenol Commercial", Supplier Part Number 1=GSB4112312HR-ND
J17: "Header, 3-Pin"
JP1 JP2: library part 000-Jumper-Short, "Jumper Wire"
L2 L8 L9 L10: "(-55 to 125 DegC AEC) FERRITE BEAD 600ohm 1206 2.5A 50mohm R@1A@150MHz:40.7ohm", Mfr="Wurth Electronics", MfrNo=78279221601, Supplier Part Number 1=732-78279221601CT-ND
L3 L4 L5 L6 L7 L15 L16 L17 L24 L25 L26 L27 L28 L29 L30 L31 L32 L33 L34 L40: "(-55 to 125 DegC) FERRITE BEAD 330 OHM 0603 1.7A 80mohm, typ 48mohm", Mfr="TDK Corporation", MfrNo=MPZ1608S331ATA00, Supplier Part Number 1=445-5221-1-ND
L11: library part 1618-Ind-1210-1uH/5.5A, "(-40 to 125 DegC) FIXED IND 1UH I:5.5A Isat:6.5A 32mohm max 26mohm typ, full-shield SMD 1210", Mfr=Bourns, MfrNo=SRP3212-1R0M, Supplier Part Number 1=118-SRP3212-1R0MCT-ND
L12: library part 0598-Ind-10x6-60ohm/15A-Choke, "(-40 to 125 DegC) CMC Choke 15A  60OHM 10x6x4mm 15A 0.7mohm", Mfr="Laird-Signal Integrity Products", MfrNo=CM3421Y600R-10, Supplier Part Number 1=240-2501-1-ND
L13: library part 1638-Ind-7x7x3-4.7uH-5.5A, "(-55 to 125 DegC) FIXED IND 4.7UH FullShield 5.5A, 9A sat 40mohm 7.3x6.6x3.0mm", Mfr=Pulse, Supplier Part Number 1=553-BMRA000606304R7MA1CT-ND
L14: library part 1872-Ind-12x12x8-15uH-5A, "(-40 to 125 DegC) FIXED IND 15UH, 5A, 9.6A sat, 25mohm FullShield 12.5x12.5x8mm", Mfr="Eaton Cooper", Supplier Part Number 1=513-1040-1-ND
L18: library part 0277-Ind-2x1.2-90ohm/0.4A-Choke, "INDUCTOR COMMON MODE 90 OHM 0.4A 0.3ohm", Mfr="Bourns Inc.", MfrNo=SRF2012-900YA, Supplier Part Number 1=SRF2012-900YACT-ND
L35 L36 L37 L38 L39: library part 1371-Ind-0.8x0.6-12ohm/0.1A-Choke, "(-40 to 85 DegC) Ind CMC Choke 12 Ohm 0.1A 1ohm 0.85x0.65x0.5mm", Mfr=Panasonic, MfrNo=EXC-14CH120U, Supplier Part Number 1=P19438CT-ND
LBL1: library part 000-Label-10x10mm, "Label for serial number 10x10mm"
LBL2: library part 000-Label-0.25x0.9IN, "Label for Toradex serial number label 0.25x0.9 inch"
LP1: library part "2302-Lightpipe Lumex LPF-S014331S", "Lightpipe R/A for 1210 size LEDs. 3.2mm x 1.8mm lens size. Board mount, press fit.", Mfr=Lumex, Supplier Part Number 1=67-1860-ND
M1: library part 1140-Conn-Toradex-Verdin, "(-55 to 85 DegC) CONN DDR4 SODIMM 260P 5.2H STD", Mfr="TE Connectivity", Supplier Part Number 1=A141326CT-ND
ME1 ME2: library part 1412-Post-M2-7mm, "(-55 to 155 DegC) ROUND STANDOFF M2X0.4 STEEL 7MM for Verdin", Mfr="Wurth Electronics", Supplier Part Number 1=732-7107-2-ND
ME3 ME4: library part 1141-Post-M2-2.5mm, "(-55 to 155 DegC) ROUND STANDOFF M2X0.4 STEEL 2.5MM for Verdin", Mfr="Wurth Electronics", Supplier Part Number 1=732-7079-1-ND
MECH1: "Toradex_Logo"
PR1 PR2 PR3 PR4: library part 1078-PhotoRelay-TLP241A, "(-40 to 85 DegC) SSR RELAY SPST-NO 2A 0-40V 90mOhm typ 5x12.5mm", Mfr=Toshiba, MfrNo=TLP241A(TP1,F, Supplier Part Number 1=TLP241A(TP1FCT-ND
PTC1 PTC2 PTC3 PTC4 PTC5 PTC6 PTC7 PTC8: library part 1423-PTC-0.1A-60V-1812, "(-40 to 85 DegC) PTC Ih:0.1A, It:0.3A, 60V, 1812, 1.6-15ohm", Mfr=Bel, MfrNo=0ZCG0010FF2C, Supplier Part Number 1=507-1754-1-ND
Q1 Q2 Q3 Q4 Q9 Q10 Q11 Q14 Q15: library part 1146-NTZD3154NT1G, "(-55 to 150 DegC) MOSFET 2N-CH (dual) 20V 0.54A SOT-563 1.6x1.6mm Vth:1V Ron typ:400m@4.5V, 500m@2.5V, 700m@1.8V", Mfr="ON Semiconductor", MfrNo=NTZD3154NT1G, Supplier Part Number 1=NTZD3154NT1GOSCT-ND
Q5 Q6 Q7 Q8 Q13: library part 0761-FDV301N, "(-55 to 155 DegC) MOSFET N-CH 25V 220MA SOT-23 Vth:1.1V Ron typ:4ohm@3V Vgsm:8V", Mfr="Fairchild/ON Semiconductor", Supplier Part Number 1=FDV301NCT-ND
R1 R2 R123 R124 R125 R126 R190: "(-55 to 155 DegC AEC) RES 120 OHM 1% 1/16W 100ppm 0402", Mfr="Stackpole Electronics", MfrNo=RMCF0402FT120R, Supplier Part Number 1=RMCF0402FT120RCT-ND
R3 R55 R66 R131 R214: "(-55 to 155 DegC) RES SMD 1M OHM 5% 0.25W 10ppm 1206", Mfr="TE Connectivity", MfrNo=CRGCQ1206J1M0, Supplier Part Number 1=A130195CT-ND
R4 R36 R37 R51 R53 R54 R57 R58 R61 R62 R63 R106 R107 R108 R109 R133 R141 R146 R223: "(-55 to 155 DegC AEC) RES 27K OHM 1% 1/16W 100ppm 0402", Mfr="Stackpole Electronics", MfrNo=RMCF0402FT27K0, Supplier Part Number 1=RMCF0402FT27K0CT-ND
R5: "(-55 to 155 DegC) RES 0.0 OHM 1/10W JUMP 0603", Mfr=Samsung, MfrNo=RC1608J000CS, Supplier Part Number 1=1276-3510-1-ND
R6 R22 R29 R31 R59 R60 R132 R154 R157: "RES 0603"
R7 R88 R89 R176 R178 R188 R192: "(-55 to 155 DegC AEC) RES 1K OHM 1% 1/16W 100ppm 0402", Mfr="TE Connectivity", MfrNo=CRGCQ0402F1K0, Supplier Part Number 1=A129627CT-ND
R8 R94 R95 R96 R97 R138 R148: "(-55 to 155 DegC) RES SMD 60.4 OHM 1% 1/10W 0603", Mfr=Bourns, MfrNo=CR0603-FX-60R4ELF, Supplier Part Number 1=652-CR0603FX-60R4ELF
R9 R10 R12 R13 R15 R16 R17 R18 R24 R25 R26 R28 R30 R39 R67 R70 R71 R74 R75 R78 R79 R81 R149 R166 R167 R197 R198 R200 R202 R206 R210 R211 R212 R215 R221 R222 R225 R226 R227 R228 R263 R272 R273 R274 R275 R276: "(-55 to 155 DegC AEC) RES 10K OHM 1% 1/16W 100ppm 0402", Mfr="Stackpole Electronics", MfrNo=RMCF0402FT10K0, Supplier Part Number 1=RMCF0402FT10K0CT-ND
R11 R40 R68 R72 R73 R77 R80 R83 R85 R98 R99 R100 R101 R135 R140 R147 R151 R152 R153 R160 R161 R162 R163 R183 R184 R193 R194 R204 R205 R207 R208 R220 R224: "(-55 to 155 DegC AEC) RES 1.87K OHM 1% 1/16W 100ppm 0402", Mfr="Stackpole Electronics", MfrNo=RMCF0402FT1K87, Supplier Part Number 1=RMCF0402FT1K87CT-ND
R14 R27 R86 R87 R127 R177 R179 R187 R191: "(-55 to 155 DegC) RES 100K OHM 1/16W 1% 0402 SMD", Mfr=Yageo, MfrNo=RC0402FR-07100KL, Supplier Part Number 1=311-100KLRCT-ND
R19 R20: "(-55 to 155 DegC) RES 100 OHM 1/10W 1% 0603", Mfr=Yageo, MfrNo=RC0603FR-07100RL, Supplier Part Number 1=311-100HRCT-ND
R21: "(-55 to 155 DegC) RES 6.04K OHM 1/10W 1% 0402 SMD", Mfr=Panasonic, MfrNo=ERJ-2RKF6041X, Supplier Part Number 1=P6.04KLCT-ND
R23 R92 R93 R119 R142 R143 R144 R145 R209 R217 R218 R219 R229 R230 R231 R232: "RES 0.0 OHM 1/10W JUMP 0603", Mfr=Samsung, MfrNo=RC1608J000CS, Supplier Part Number 1=1276-3510-1-ND
R32 R48 R134 R182: "(-55 to 155 DegC) RES SMD 200K 1% 1/10W 0603 100ppm", Mfr="Stackpole Electronics", MfrNo=RMCF0603FT200K, Supplier Part Number 1=RMCF0603FT200KCT-ND
R33 R34 R42 R45 R46 R84 R174 R175: "(-55 to 155 DegC AEC) RES 86.6K OHM 1% 1/16W 100ppm 0402", Mfr="Stackpole Electronics", MfrNo=RMCF0402FT86K6, Supplier Part Number 1=RMCF0402FT86K6CT-ND
R35 R38 R52 R56 R121 R129 R139 R150 R185: "(-55 to 155 DegC AEC) RES 12K OHM 1% 1/16W 100ppm 0402", Mfr="Stackpole Electronics", MfrNo=RMCF0402FT12K0, Supplier Part Number 1=RMCF0402FT12K0CT-ND
R41 R43: "(-55 to 155 DegC AEC) RES 6.49K OHM 1% 0.25W 0805 100ppm", Mfr="KOA Speer", MfrNo=RK73H2ATTD6491F, Supplier Part Number 1=2019-RK73H2ATTD6491FCT-ND
R44: "(-55 to 155 DegC AEC) RES SMD 560K 1% 1/10W 0603 100ppm", Mfr="Stackpole Electronics", MfrNo=RMCF0603FT560K, Supplier Part Number 1=RMCF0603FT560KCT-ND
R47 R49 R50 R69 R76 R82 R136 R137 R168 R169 R170 R171 R172 R173 R180 R181 R203 R264 R269 R270 R271: "(-55 to 155 DegC) RES 4.70K OHM 1/16W 1% 0402 100ppm", Mfr=Yageo, MfrNo=RC0402FR-074K7L, Supplier Part Number 1=311-4.7KLRCT-ND
R64: "(-55 to 155 DegC AEC) RES 887K OHM 1% 1/16W 100ppm 0402", Mfr="Stackpole Electronics", MfrNo=RMCF0402FT887K
R65 R155 R195 R196: "RES SMD 274 OHM 1% 1/10W 0603", Mfr=Yageo, MfrNo=RC0603FR-07274RL, Supplier Part Number 1=311-274HRCT-ND
R90 R91 R189 R233 R234 R235 R236 R237 R238 R239 R240 R241 R242 R243 R244 R245 R246 R247 R248 R249 R250 R251 R252 R253 R254 R255 R256 R257 R258 R259 R260 R261 R262: "(-55 to 155 DegC) RES 0.0 OHM 1/4W JUMPER 1206", Mfr=TE, MfrNo=1623693-1, Supplier Part Number 1=A106079CT-ND
R102 R103 R104 R105: "RES SMD 680 OHM 1% 1/10W 0603", Mfr=Yageo, MfrNo=RC0603FR-07680RL, Supplier Part Number 1=311-680HRCT-ND
R110 R111 R112 R113: "(-55 to 155 DegC) RES SMD 10 OHM 5% 2W Pulse 2512", Mfr=Bourns, MfrNo=CRM2512AJW-100ELF, Supplier Part Number 1=CRM2512AJW-100ELFCT-ND
R114 R118: "(-55 to 155 DegC) RES SMD 2.49K OHM 1% 1/16W 0402 100ppm", Mfr=Yageo, MfrNo=RC0402FR-072K49L, Supplier Part Number 1=311-2.49KLRCT-ND
R115 R120: "(-55 to 155 DegC) RES 5.76K OHM 1/16W 1% 0402 SMD", Mfr="Stackpole Electronics", MfrNo=RMCF0402FT5K76, Supplier Part Number 1=RMCF0402FT5K76CT-ND
R116 R117 R199 R201 R265 R266 R267 R268: "RES 0402"
R122: "(-55 to 155 DegC AEC) RES SMD 11K OHM 1% 1/16W 0402 100ppm 0402", Mfr=Yageo, MfrNo=AC0402FR-0711KL, Supplier Part Number 1=YAG3439CT-ND
R128 R156: "RES 47.0K OHM 1/10W 1% 0603 SMD", Mfr=Yageo, MfrNo=RC0603FR-0747KL, Supplier Part Number 1=311-47.0KHRCT-ND
R130: "(-55 to 155 DegC) RES 47.0K OHM 1/10W 1% 0603 SMD", Mfr=Yageo, MfrNo=RC0603FR-0747KL, Supplier Part Number 1=311-47.0KHRCT-ND
R158 R159: "RES SMD 100 OHM 0.01% 0.5W 1206 5ppm", Mfr="Stackpole Electronics", MfrNo=RNCF1206TKY100R, Supplier Part Number 1=RNCF1206TKY100RCT-ND
R164 R165 R186: "(-55 to 155 DegC) RES SMD 6.49K OHM 1% 1/16W 0402", Mfr=Yageo, MfrNo=RC0402FR-076K49L, Supplier Part Number 1=311-6.49KLRCT-ND
R213 R216: "RES SMD 6.8K OHM 1% 1/10W 0603", Mfr=Yageo, MfrNo=RC0603FR-076K8L, Supplier Part Number 1=311-6.80KHRCT-ND
RA1 RA2: "(-55 to 125 DegC) RES ARRAY 4 RES 10K 1% 200ppm 1206", Mfr=Yageo, MfrNo=TC164-FR-0710KL, Supplier Part Number 1=RAVF164DJT10K0CT-ND
RA6 RA7: "(-55 to 125 DegC) RES ARRAY 4 RES 10 kOHM 30 kOHM 1206", Mfr="Vishay Beyschlag", MfrNo=ACASA1002S3002P100, Supplier Part Number 1=749-1027-1-ND
S1 S2: library part "1226-Push Button", "(-30 to 85 DegC) SWITCH TACTILE SPST-NO Push Button RA 4.5x2.8x4.5mm", Mfr="XKB Connectivity", MfrNo=TC-1109DE-C-A
U1 U2 U15 U27 U28 U34 U36 U69 U70 U71: library part 1657-DT1240-04LP-7, "(-55 to 85 DegC) IC TVS DIODE 4ch Vrm:5.5V Vcl:11V@5.5A 10-UFDFN 0.5mm", Mfr=Diodes, Supplier Part Number 1=DT1240-04LP-7DICT-ND
U3: library part 1361-SLM9670, "(-40 to 105 DegC) IC Trusted Platform TPM SECURITY 32-VFQFN", Mfr=Infineon, Supplier Part Number 1=SLM9670AQ20FW1311XTMA1CT-ND
U4 U33 U66 U67: library part 0740-TPD4E001, "(-40 to 125 DegC AEC) TVS DIODE 5.5VWM 16VC SOT-23-6", Mfr="Texas Instruments", MfrNo=TPD4E001QDBVRQ1, Supplier Part Number 1=296-39344-1-ND
U5: library part 1679-M24C02-FMC6TG, "(-40 to 85 DegC) IC EEPROM 2KBIT (256B) 400KHZ 1.7-5.5V adr 0x50-57 2x3mm 8-UFDFN", Mfr=STMicroelectronics, Supplier Part Number 1=497-15747-1-ND
U6: library part 1877-MB85RS256TY, "(-40 to 125 DegC) IC FRAM Memory 1.8-3.6V 256Kbit 32x8KB SPI 33 MHz 8-SOIC", Mfr=Fujitsu, Supplier Part Number 1=865-1293-1-ND
U7: library part 1853-TMP1075DSGR, "(-55 to 125 DegC) IC Temp Sensor I2C 1.7-5.5V WSON8", Mfr="Texas Instruments", Supplier Part Number 1=296-TMP1075DSGRCT-ND
U8: library part 2096-CYUSB3304-68LTXI, "(-40 to 85 DegC) IC USB 3.0 HUB 4-PORT 68QFN", Mfr="Infineon Technologies", Supplier Part Number 1=448-CYUSB3304-68LTXI-ND
U9 U29 U30 U65: library part 1467-AP2132BMP-2.5, "(-40 to 85 DegC) IC REG LDO LINEAR POS ADJ 5V 2A 8SO", Mfr=Diodes, Supplier Part Number 1=AP2132BMP-2.5TRG1DICT-ND
U10: library part 1619-TPS62823, "(-40 to 125 DegC) IC  IC REG BUCK ADJ 2.2MHz Vin:2.4-5.5V Io:3A Sync 8-VFDFN 8VSON-HR", Mfr="Texas Instruments", Supplier Part Number 1=296-50425-1-ND
U11: library part 1362-AP64500SP-13, "(-40 to 85 DegC) IC REG BUCK ADJ Sync 5A Vin:3.8 to 40V 100-2200kHz FSS (spread spectrum) MaxDuty:100% SO-8EP", Mfr=Diodes, Supplier Part Number 1=31-AP64500SP-13CT-ND
U12: library part 2063-LM5013DDAR, "(-40 to 150 DegC) IC REG BUCK ADJ 3.5A 8-POWERSOIC 1MHz 100V", Mfr="Texas Instruments", Supplier Part Number 1=296-LM5013DDARCT-ND
U13: library part 1458-TUSB320LI, "(-40 to 85 DegC) IC USB TYPE-C CC LOGIC AND PORT Control 12-X2QFN", Mfr="Texas Instruments", Supplier Part Number 1=296-42544-1-ND
U14: library part 1469-BD2222G, "(-40 to 85 DegC) IC PWR SWITCH 2.8-5.5V EN-Active-High ENth:2.0V No-Discharge 89mohm typ ADJ 0.2-1.7A 6SSOP", Mfr=Rohm, MfrNo=BD2222G-GTR, Supplier Part Number 1=846-BD2222G-GTRCT-ND
U16 U48: library part 2540-SN74AXC8T245RJWR, "(-40 to 125 DegC) IC TRANSLATION TXRX 0.65-3.6V 24UQFN", Mfr="Texas Instruments", Supplier Part Number 1=595-SN74AXC8T245RJWR
U18 U19 U44 U46 U49 U53: library part 2065-UCC12040DVER, "(-40 to 125 DegC) IC Isolated DC DC Converter-Output 3.3V, 5V 140mA, 4.5V-5.5V Input", Mfr="Texas Instruments", Supplier Part Number 1=595-UCC12040DVER
U20 U21 U50 U51 U54 U55: library part 2198-ISO6721RBDR, "(-40 to 125 DegC) IC DGTL ISO GENERAL-PURPOSE, DUAL-CHANNEL, 1x In, 1x Out 1.71-5.5V", Mfr="Texas Instruments", Supplier Part Number 1=595-ISO6721RBDR
U22 U23: library part 1620-TCAN1044VDRQ1, "(-40 to 125 DegC) IC TXRX CAN FD 8MBPS Vio:1.8-5V Standby 8SOIC", Mfr="Texas Instruments", Supplier Part Number 1=296-TCAN1044VDRQ1CT-ND
U24 U25: library part 1564-ESDCAN06-2BWY, "(-55 to 175 DegC AEC) TVS DIODE CAN 2-ch 35V Vcl: 59Vmax, 8/20:3A, ESD:30KV air,30KV cont, 15pF, SOT323", Mfr=STMicroelectronics, Supplier Part Number 1=497-17304-1-ND
U26: library part 2076-DP83867ERGZR, "(-40 to 105 DegC) Eth Phy RGMII 1GBASE-T VQFN-48", Mfr="Texas Instruments", Supplier Part Number 1=595-DP83867ERGZR
U31 U47: library part 0972-PCA9306DCT, "(-40 to 85 DegC) IC TRANSLTR BIDIRECTIONAL I2C SM8", Mfr="Texas Instruments", MfrNo=PCA9306DCTR, Supplier Part Number 1=296-18509-1-ND
U32: library part 1467-AP2132BMP-2.5, "(-40 to 85 DegC) IC REG LDO LINEAR POS ADJ 5V 2A 8SO", Mfr=Diodes, MfrNo=AP2132BMP-2.5TRG1, Supplier Part Number 1=AP2132BMP-2.5TRG1DICT-ND
U35 U64 U68: library part 1475-AP22653, "(-40 to 85 DegC) IC PWR SWITCH 3-5.5V EN-Active-High ENth:1.5V With-Discharge 65mohm typ ADJ 0.1-2.1A 6SSOP", Mfr=Diodes, Supplier Part Number 1=31-AP22653AW6-7CT-ND
U37 U38: library part 1870-TPS26614, "(-40 to 155 DegC) IC Current Loop Protector 50V TSOT-23-8", Mfr="Texas Instruments", Supplier Part Number 1=296-TPS26614DDFRCT-ND
U39 U40: library part 1414-ADS1119, "(-40 to 125 DegC) IC ADC 16BIT 4ch 1000SPS 16-TSSOP I2C Adr 0x40-0x4F IntRef SigmaDelta", Mfr="Texas Instruments", MfrNo=ADS1119IPWR, Supplier Part Number 1=296-50874-1-ND
U41 U42: library part 0619-AP2202K-ADJ, "(-40 to 125 DegC) IC REG LDO ADJ 0.15A SOT23-5 13.2V", Mfr="Diodes Incorporated", MfrNo=AP2202K-ADJTRG1, Supplier Part Number 1=AP2202K-ADJTRG1DICT-ND
U43 U45: library part 2064-ISO1644DWR, "(-40 to 125 DegC) DGTL ISO 5KV 5CH I2C 16SOIC", Mfr="Texas Instruments", Supplier Part Number 1=296-ISO1644DWRTR-ND
U52: library part 2071-SN65176BDR, "(-40 to 125 DegC) IC TXRX 5V RS485/422 8-SOIC", Mfr="Texas Instruments", Supplier Part Number 1=296-14636-2-ND
U56: library part 0156-ST3232BTR, "IC DRVR/RCVR RS232 LP 16-TSSOP", Mfr=ST, Supplier Part Number 1=497-6534-1-ND
U57 U58 U59: library part 2239-PESD15VL2BT,215, "(-65 to 150 DegC) TVS DIODE 2-CH 15VWM 44VC ESD:30KV TO236AB", Mfr=Nexperia, Supplier Part Number 1=1727-3813-1-ND
U60 U61: library part 0394-PSSI2021, "(-65 to 150 DegC AEC)  IC CURRENT SOURCE SOT353 75V 50uA-50mA", Mfr="Nexperia USA Inc.", MfrNo=PSSI2021SAY,115, Supplier Part Number 1=1727-4328-1-ND
U62 U63: library part 1170-Opto-TLP185GR, "OPTOISO 3.75KV TRANS 6-SO 4 LEAD TR:100-300%@5mA, 80V, 3.7x7mm", Mfr=Toshiba, MfrNo=TLP185(GR-TPL,SE, Supplier Part Number 1=TLP185(GR-TPLSECT-ND
X8 X13 X14 X20 X21 X22 X23 X24 X51 X52 X53 X55 X56 X57 X80 X81: "TestPoint SMD"
XS1: library part 1028-Conn-BatHolder-1220, "(-40 to 105 DegC) Battery Holder Coin 12mm SMD 1216/1220/1225", Mfr="Keystone Electronics", MfrNo=3000, Supplier Part Number 1=36-3000-ND
Y1: "(-40 to 85 DegC) XTAL CRYSTAL 26.0000MHZ 12PF SMD +-15ppm +-10ppm 2.0x1.6mm", Mfr="Murata Electronics", MfrNo=XRCGB26M000F1SADR0, Supplier Part Number 1=490-XRCGB26M000F1SADR0TR-ND
Y2: "(-40 to 85 DegC) CRYSTAL 25.0MHZ 18PF SMD +-50ppm +-20ppm 3.2x2.5mm", Mfr="IQD Frequency Products", MfrNo=LFXTAL055299REEL, Supplier Part Number 1=1923-1305-1-ND

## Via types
v1: diameter 0.6, hole 0.3, Top Layer to Bottom Layer, tented both sides, 1130 vias
v2: diameter 0.6, hole 0.3, Top Layer to Bottom Layer, 53 vias
v3: diameter 0.3, hole 0.3, Top Layer to Bottom Layer, 12 vias

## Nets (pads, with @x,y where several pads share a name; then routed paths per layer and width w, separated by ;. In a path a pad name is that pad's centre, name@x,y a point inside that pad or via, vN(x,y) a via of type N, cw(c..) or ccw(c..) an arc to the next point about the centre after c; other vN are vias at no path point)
1V0_ETH: C133.2 C134.2 C136.2 C138.2 C141.2 C145.2 C148.2 C151.2 C154.2 C166.2 R129.2 U26.6 U26.24 U26.31 U26.42 U30.6 X53.1 | length 19.1
  Top Layer w0.15: C134.2@51.45,23.75 51.625,23.925 51.775,23.925 v1(52.15,24.3) 52.028,24.3 51.903,24.425 51.625,24.425 C145.2@51.45,24.6
  Top Layer w0.5: C154.2@43.775,26.503 44.353,26.503 44.6,26.75 v1(44.6,27.4) 43.779,27.4 C141.2@43.775,27.403 ; C136.2@46.7,19.95 C133.2@47.55,19.95 v1(48.25,19.95) C148.2@48.95,19.95 ; v1(48.236,28.157) 48.25,28.171 C138.2@48.25,28.9 ; v1@48.25,28.15 48.95,28.15 49.1,28.3 C151.2@49.1,28.9
  Bottom Layer w0.15: X53.1@62.4,18.05 R129.2@62.4,19.345 63.075,19.345 63.42,19 v1(65.75,19)
  Bottom Layer w0.2: U26.24@44.6,26.825 v1(44.6,27.4) ; v1(48.236,28.157) 48.243,28.15 48.243,27.482 U26.31@48.25,27.475 ; v1(48.25,19.95) U26.6@48.25,20.675 ; U26.42@51.4,24.325 52.125,24.325 v1(52.15,24.3)
  Bottom Layer w0.5: v1(65.75,19) C166.2@65.75,19.8 65.75,21.88 U30.6@65.77,21.9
